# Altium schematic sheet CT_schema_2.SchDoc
size 298 x 230 mm
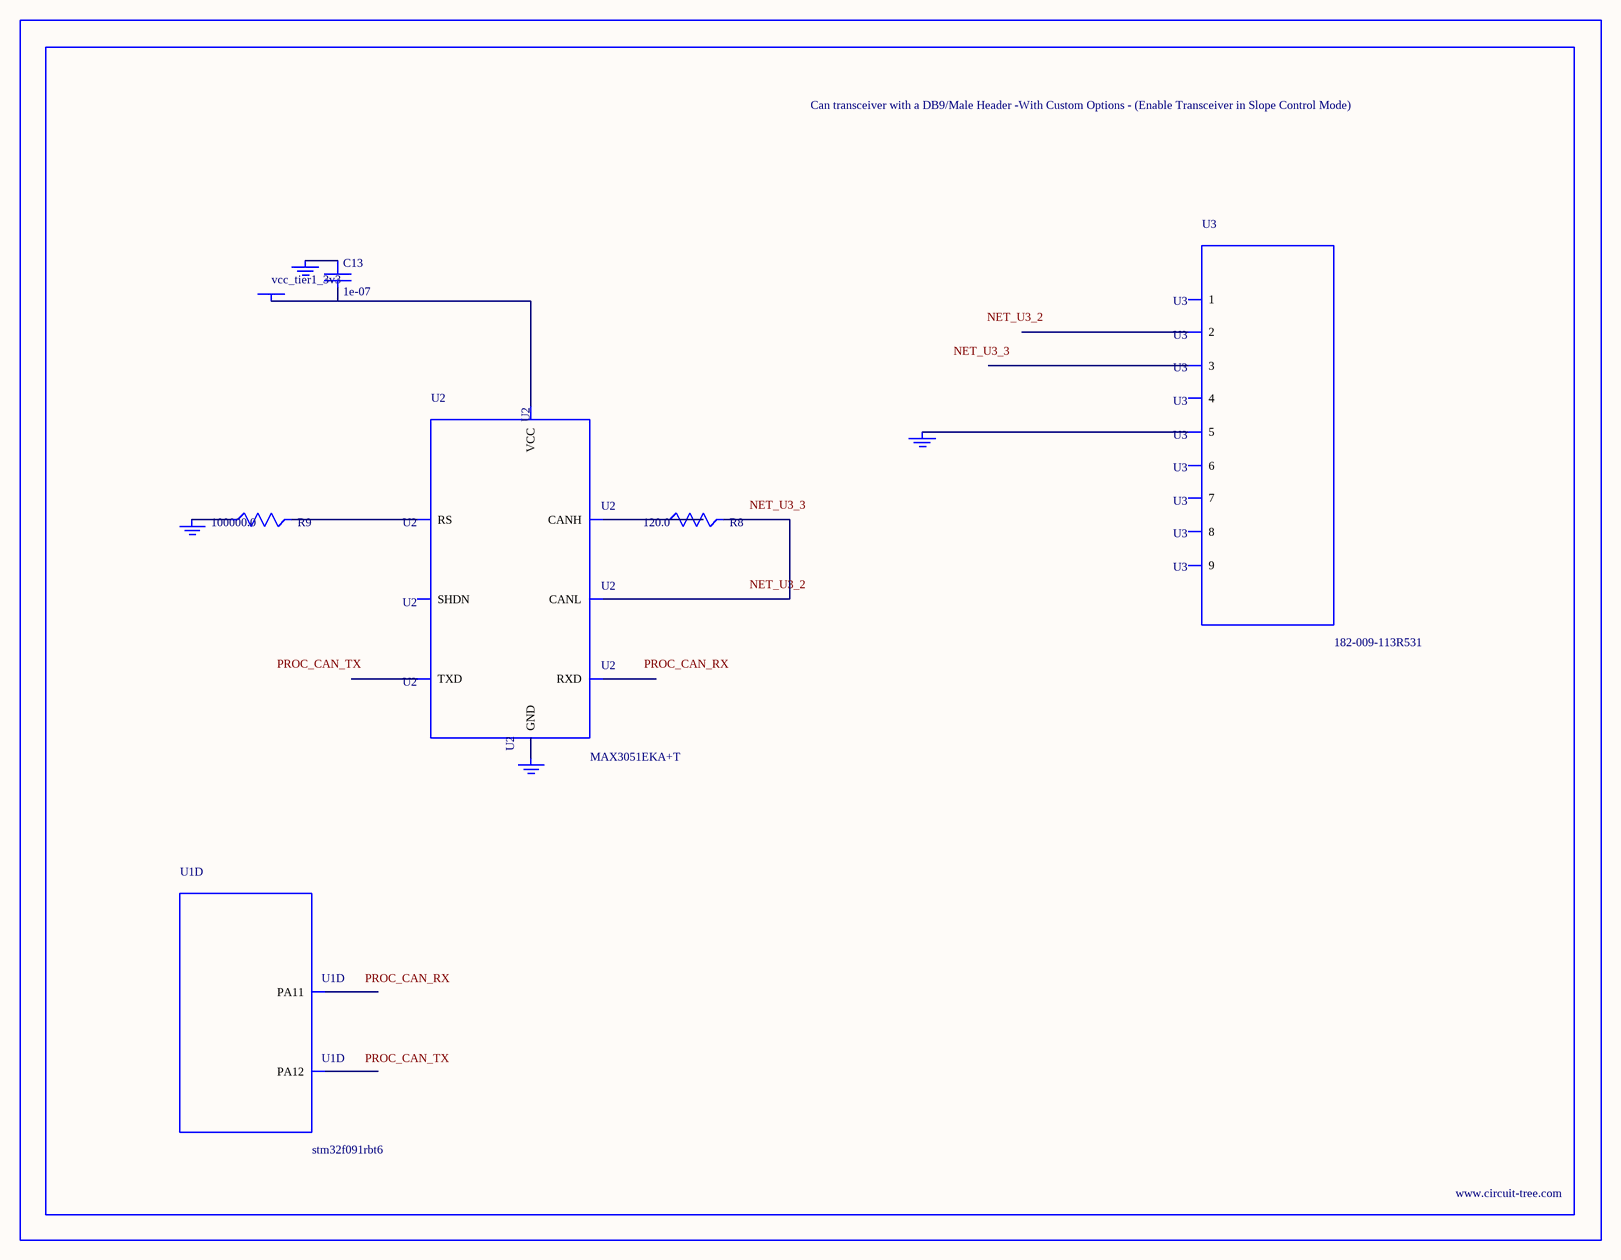
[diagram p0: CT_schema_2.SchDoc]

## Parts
BORDER1  (no value)
C13  1e-07  [C0402]
GND_INSTANCE_1_0  (no value)
GND_INSTANCE_1_1  (no value)
GND_INSTANCE_1_2  (no value)
GND_INSTANCE_1_3  (no value)
POWER_INSTANCE_1_0  vcc_tier1_3v3
R8  120.0  [R0603]
R9  100000.0  [R0603]
U1  stm32f091rbt6  [LQFP64]  (part D of 6)
U2  MAX3051EKA+T  [SOT-23-8]
U3  182-009-113R531  [182-009-MALE]

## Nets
NetC13_1: C13.1 GND_INSTANCE_1_0.0(GND)
NetC13_2: C13.2 POWER_INSTANCE_1_0.0(PWR) U2.3(VCC)
NetGND_INSTANCE_1_1_0: GND_INSTANCE_1_1.0(GND) R9.1
NetGND_INSTANCE_1_2_0: GND_INSTANCE_1_2.0(GND) U2.2(GND)
NetGND_INSTANCE_1_3_0: GND_INSTANCE_1_3.0(GND) U3.5
NetR8_1: R8.1 U2.7(CANH)
NetR8_2: R8.2 U2.6(CANL)
NetR9_2: R9.2 U2.8(RS)

Not connected (* = marked no-connect by the designer): U1 44(PA11) 45(PA12); U2 1(TXD) 4(RXD) 5(SHDN); U3 1 2 3 4 6 7 8 9

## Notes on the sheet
- Labels drawn without touching a wire or pin: NET_U3_2, NET_U3_3, PROC_CAN_RX, PROC_CAN_TX

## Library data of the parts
BORDER1 = BORDER_PAGE1
C13 = C0402C104K3RACTU
GND_INSTANCE_1_0-GND_INSTANCE_1_3 = GND
POWER_INSTANCE_1_0 = PWR
R8 = RC0603JR-07120RL
R9 = RC0603JR-07100KL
